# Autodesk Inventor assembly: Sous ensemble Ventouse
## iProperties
Created: 2004-11
Part Number: Sous ensemble Ventouse
Document SubType Name: Assembly
Designer: Bruno
Manufacturer: Standard
Standards Organization: Custom
Norme de conversion: STEP AP203
Nom du fichier: Take Out.stp
Préprocesseur: Mechanical Desktop 2005
Postprocesseur: Build: 096e, Release: 9 RTM - Date: Thu 06/17/2004
Unités envoyées: MILLIMETERS
Incertitude: 1.0000000000000002e-06
Author: Bruno
